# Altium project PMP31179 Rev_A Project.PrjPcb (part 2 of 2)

## Sheet PMP31179 Rev_A LLC Schematic.SchDoc: LLC
size 431 x 317 mm; Date: Not shown in title block; ApprovedBy: Not shown in title block; CheckedBy: Not shown in title block; Author: Not shown in title block; CompanyName: Not shown in title block; DrawnBy: R. Scibilia; Engineer: R. Scibilia; Organization: Not shown in title block; Address1: Not shown in title block; Address2: Not shown in title block; Address3: Not shown in title block; Address4: Not shown in title block; DocumentNumber: 1; Revision: Use project parameter SCH_Rev; SheetNumber: 2; SheetTotal: 3; PageSetup: Record=PageOptions¦CenterHorizontal=True¦CenterVertical=True¦PrintScale=1.00¦XCorrection=1.00¦YCorrection=1.00¦PrintKind=0¦BorderSize=5000000¦LeftOffset=0¦BottomOffset=0¦Orientation=2¦PaperLength=1000¦PaperWidth=1000¦Scale=100¦PaperSource=15¦PrintQuality=600¦MediaType=1¦DitherType=10¦PaperKind=Letter¦PrintScaleMode=1
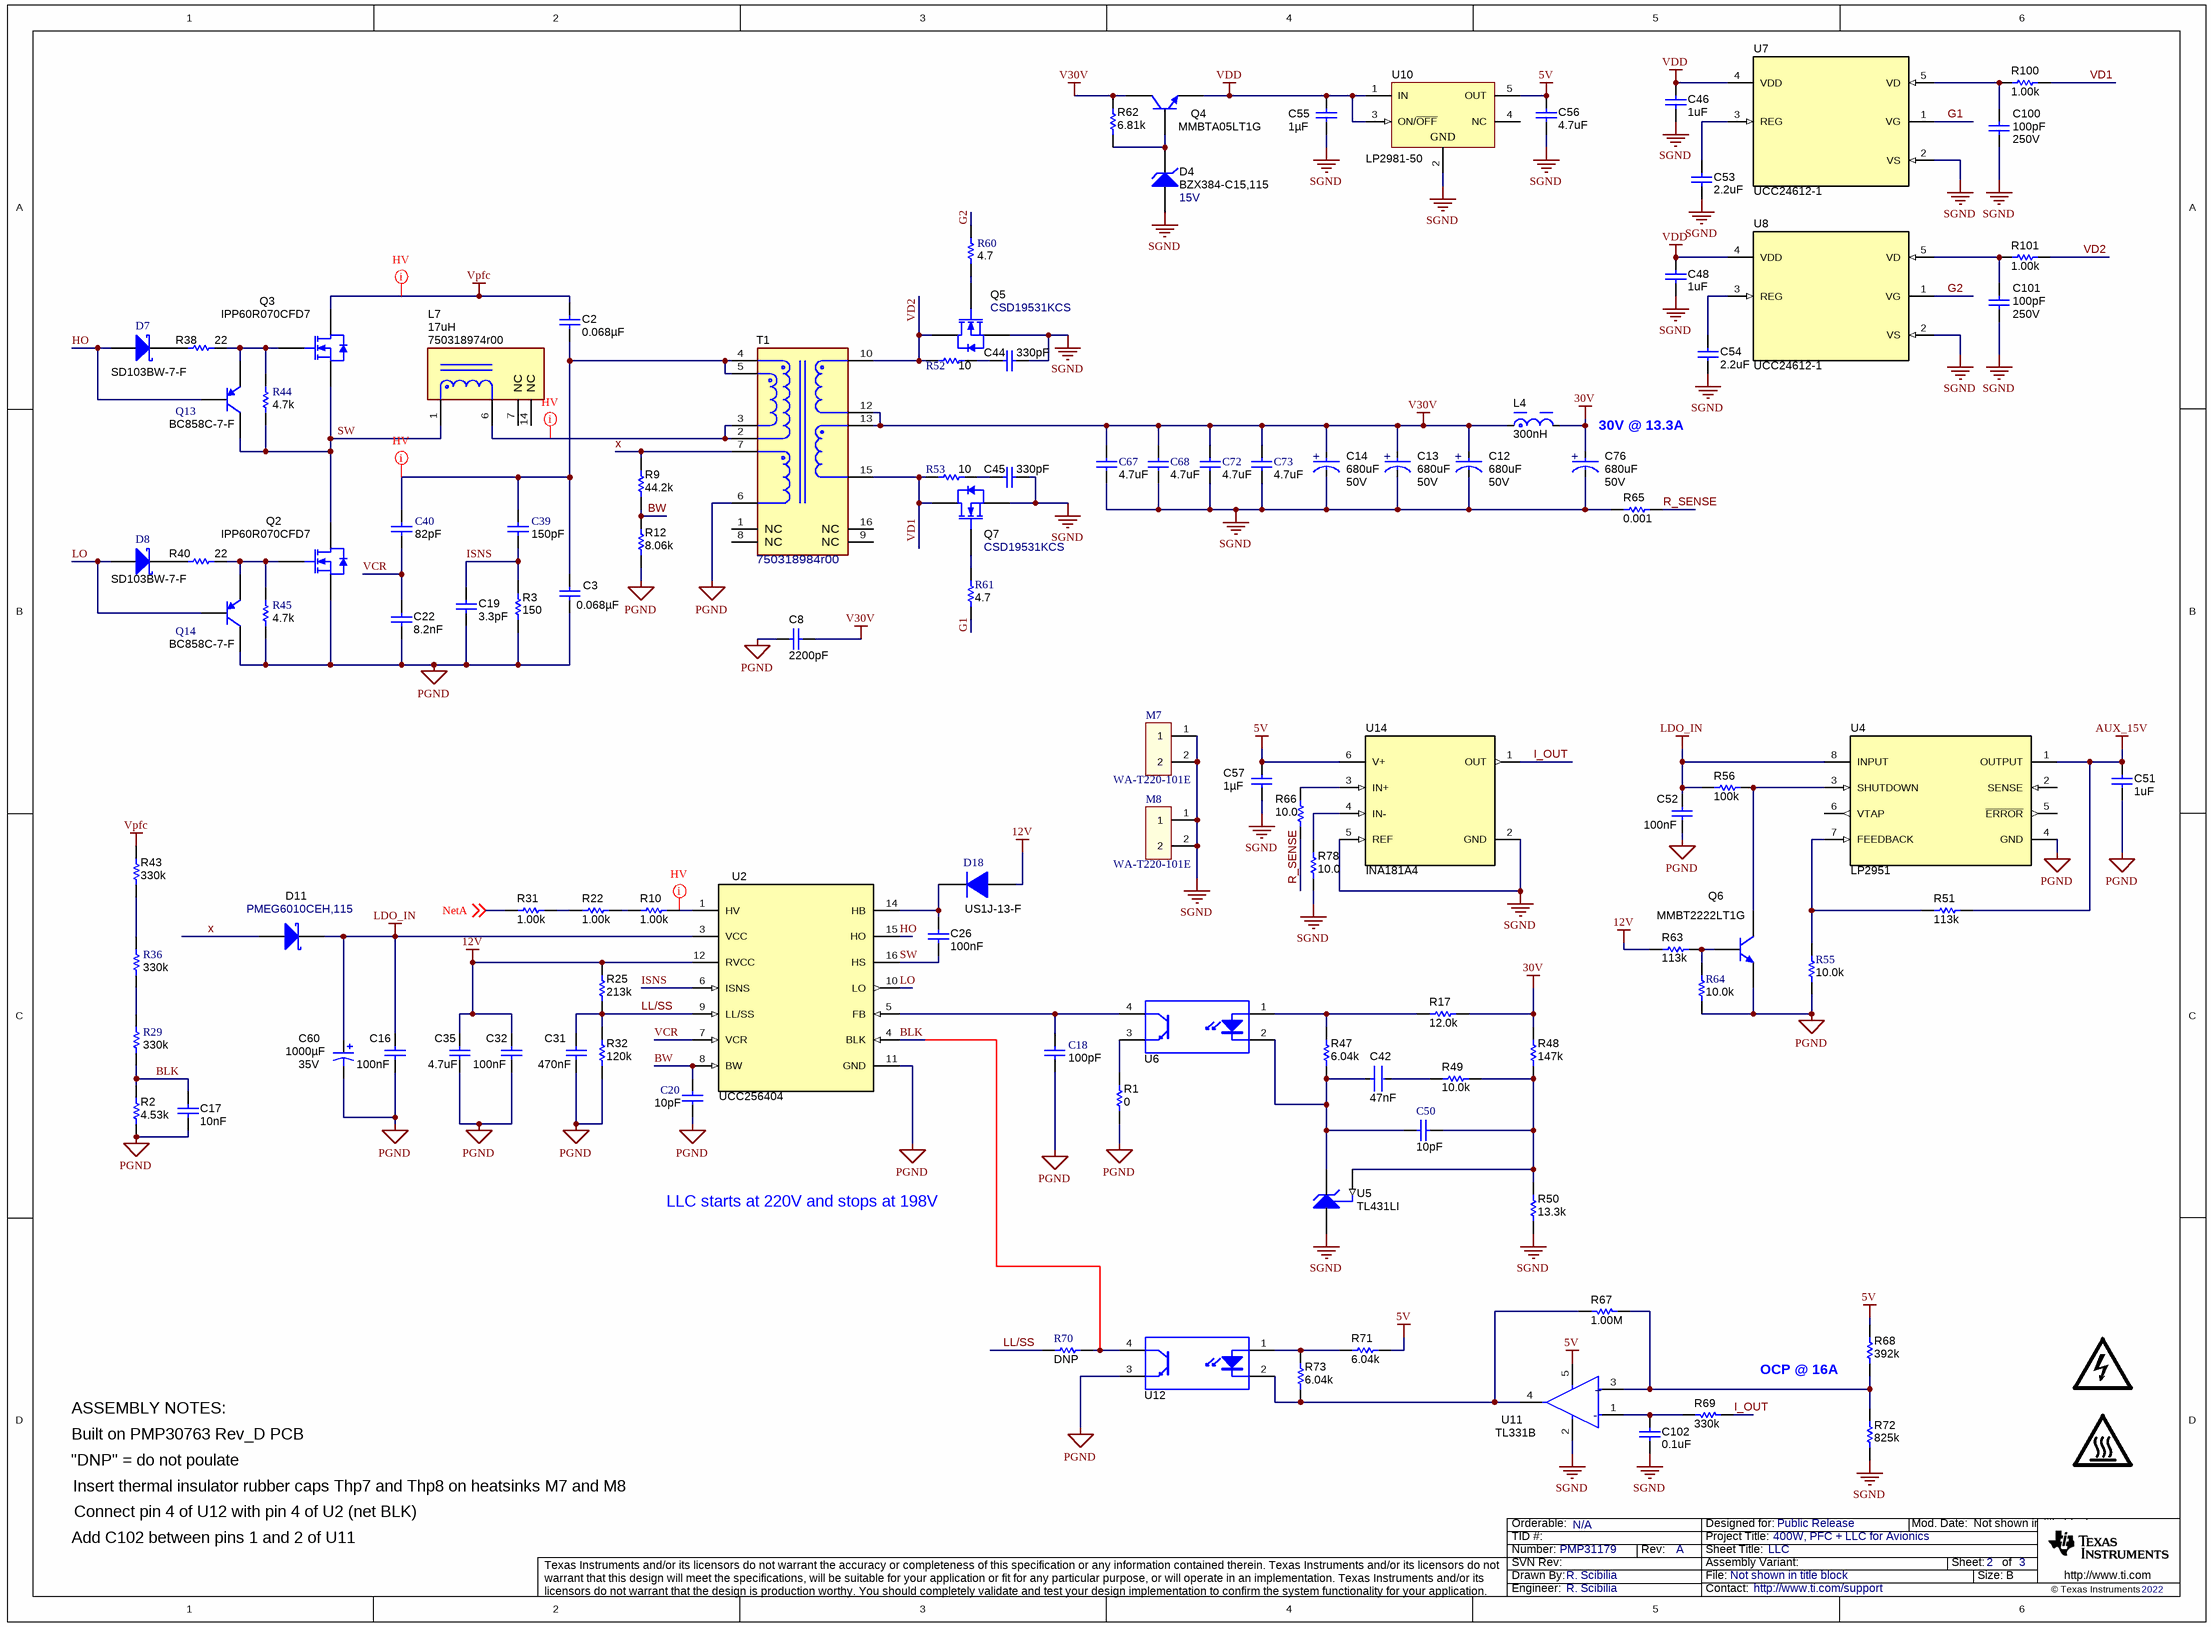
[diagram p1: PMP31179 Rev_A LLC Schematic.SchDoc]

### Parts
(Parts that share a designator on the sheet are numbered #1, #2 ... from top to bottom, then left to right.)
C2  ValueDisplayed: 0.068µF  [B32652_1800x700x1250]  (hidden comment: B32642B6683J)
C3  ValueDisplayed: 0.068µF  [B32652_1800x700x1250]  (hidden comment: B32642B6683J)
C8  ValueDisplayed: 2200pF  [AY2_950x500_Straight]  (hidden comment: Capacitor)
C12  value 680uF  VDC_V: 50V  [FP-860080678019_RADIAL-MFG]  (hidden comment: 860080678021)
C13  value 680uF  VDC_V: 50V  [FP-860080678019_RADIAL-MFG]  (hidden comment: 860080678021)
C14  value 680uF  VDC_V: 50V  [FP-860080678019_RADIAL-MFG]  (hidden comment: 860080678021)
C16  Cap_F: 100nF  [0603]  (hidden comment: 885012206095)
C17  Cap_F: 10nF  [0603]  (hidden comment: 885012206040)
C18  ValueDisplayed: 100pF  [0603]  (hidden comment: 885012006023)
C19  ValueDisplayed: 3.3pF  [0805_HV1]  (hidden comment: Capacitor)
C20  ValueDisplayed: 10pF  [0603]  (hidden comment: Capacitor)
C22  Cap_F: 8.2nF  [0603]  (hidden comment: GRM188R71H822KA01D)
C26  Cap_F: 100nF  [0805_HV]  (hidden comment: 885012207128)
C31  Cap_F: 470nF  [0805_HV]  (hidden comment: 885012207102)
C32  Cap_F: 100nF  [0603]  (hidden comment: 885012206095)
C35  ValueDisplayed: 4.7uF  [0603]  (hidden comment: GRM188R61E475KE11D)
C39  ValueDisplayed: 150pF  [1206]  (hidden comment: Capacitor)
C40  ValueDisplayed: 82pF  [1206]  (hidden comment: GRM31A7U3A820JW31D)
C42  Cap_F: 47nF  [FP-885012206069_0603-MFG]  (hidden comment: 885012206069)
C44  ValueDisplayed: 330pF  [1206]  (hidden comment: 885012008070)
C45  ValueDisplayed: 330pF  [1206]  (hidden comment: 885012008070)
C46  ValueDisplayed: 1uF  [0805_HV1]  (hidden comment: Capacitor)
C48  ValueDisplayed: 1uF  [0805_HV1]  (hidden comment: Capacitor)
C50  ValueDisplayed: 10pF  [0603]  (hidden comment: Capacitor)
C51  ValueDisplayed: 1uF  [1206]  (hidden comment: Capacitor)
C52  Cap_F: 100nF  [0603]  (hidden comment: 885012206095)
C53  ValueDisplayed: 2.2uF  [0603]  (hidden comment: GRM188R6YA225KA12D)
C54  ValueDisplayed: 2.2uF  [0603]  (hidden comment: GRM188R6YA225KA12D)
C55  Cap_F: 1µF  [0603]  (hidden comment: 885012206076)
C56  ValueDisplayed: 4.7uF  [0603]  (hidden comment: GRM188R61E475KE11D)
C57  Cap_F: 1µF  [0603]  (hidden comment: 885012206076)
C60  value 1000µF  VDC_V: 35V  [Panasonic_1000x1250]  (hidden comment: 860160575031)
C67  ValueDisplayed: 4.7uF  [1210]  (hidden comment: Capacitor)
C68  ValueDisplayed: 4.7uF  [1210]  (hidden comment: Capacitor)
C72  ValueDisplayed: 4.7uF  [1210]  (hidden comment: Capacitor)
C73  ValueDisplayed: 4.7uF  [1210]  (hidden comment: Capacitor)
C76  value 680uF  VDC_V: 50V  [FP-860080678019_RADIAL-MFG]  (hidden comment: 860080678021)
C100  VDC_V: 250V  ValueDisplayed: 100pF  [0805_HV]  (hidden comment: 885342006003)
C101  VDC_V: 250V  ValueDisplayed: 100pF  [0805_HV]  (hidden comment: 885342006003)
C102  ValueDisplayed: 0.1uF  [0805_HV1]  (hidden comment: Capacitor)
D4  BZX384-C15,115  value 15V  [SOD-323]
D7  value SD103BW-7-F  [SOD-123]  (hidden comment: DIODE_SCHOTTKY)
D8  value SD103BW-7-F  [SOD-123]  (hidden comment: DIODE_SCHOTTKY)
D11  PMEG6010CEH,115  [SOD-123F]
D18  value US1J-13-F  [SMA]  (hidden comment: DIODE)
L4  value 300nH  [FP-7443081030_SMT_IND_9MM4_6MM2-MFG]  (hidden comment: 7443081030)
L7  value 17uH  [FP-750318974r00_PTH_23MM88_23MM36-MFG]  (hidden comment: 750318974r00)
LOGO?#3  DANGER HIGH VOLTAGE  [IEC_HighVoltage_Small]  (value not drawn)  (graphical)
LOGO?#4  CAUTION HOT SURFACE  [IEC_HotSurface_Small]  (value not drawn)  (graphical)
M7  WA-T220-101E  [HEATSINK_WA-T220-101E]
M8  WA-T220-101E  [HEATSINK_WA-T220-101E]
Q2  value IPP60R070CFD7  [TO-220AB]  (hidden comment: IPP60R190P6)
Q3  value IPP60R070CFD7  [TO-220AB]  (hidden comment: IPP60R190P6)
Q4  MMBTA05LT1G  [SOT-23]
Q5  CSD19531KCS  [KCS0003B]
Q6  MMBT2222LT1G  [SOT-23]
Q7  CSD19531KCS  [KCS0003B]
Q13  BC858C-7-F  [SOT-23]
Q14  BC858C-7-F  [SOT-23]
R1  ValueDisplayed: 0  [0603]  (hidden comment: RMCF0603ZT0R00)
R2  ValueDisplayed: 4.53k  [0603]  (hidden comment: ERJ-3EKF4531V)
R3  ValueDisplayed: 150  [0805_HV]  (hidden comment: CRCW0805150RFKEA)
R9  ValueDisplayed: 44.2k  [0603]  (hidden comment: CRCW060344K2FKEA)
R10  ValueDisplayed: 1.00k  [1206]  (hidden comment: Resistor)
R12  ValueDisplayed: 8.06k  [0603]  (hidden comment: RC0603FR-078K06L)
R17  ValueDisplayed: 12.0k  [0603]  (hidden comment: RC0603FR-0712KL)
R22  ValueDisplayed: 1.00k  [1206]  (hidden comment: Resistor)
R25  ValueDisplayed: 213k  [0603]  (hidden comment: RT0603DRE07213KL)
R29  ValueDisplayed: 330k  [1206]  (hidden comment: Resistor)
R31  ValueDisplayed: 1.00k  [1206]  (hidden comment: Resistor)
R32  ValueDisplayed: 120k  [0603]  (hidden comment: RC0603FR-07120KL)
R36  ValueDisplayed: 330k  [1206]  (hidden comment: Resistor)
R38  ValueDisplayed: 22  [0603]  (hidden comment: Resistor)
R40  ValueDisplayed: 22  [0603]  (hidden comment: Resistor)
R43  ValueDisplayed: 330k  [1206]  (hidden comment: CRCW1206330KJNEA)
R44  ValueDisplayed: 4.7k  [0603]  (hidden comment: Resistor)
R45  ValueDisplayed: 4.7k  [0603]  (hidden comment: Resistor)
R47  ValueDisplayed: 6.04k  [0603]  (hidden comment: Resistor)
R48  ValueDisplayed: 147k  [0603]  (hidden comment: Resistor)
R49  ValueDisplayed: 10.0k  [0603]  (hidden comment: Resistor)
R50  ValueDisplayed: 13.3k  [0603]  (hidden comment: RC0603FR-0713K3L)
R51  ValueDisplayed: 113k  [0603]  (hidden comment: CRCW0603113KFKEA)
R52  ValueDisplayed: 10  [0805_HV1]  (hidden comment: Resistor)
R53  ValueDisplayed: 10  [0805_HV1]  (hidden comment: Resistor)
R55  ValueDisplayed: 10.0k  [0603]  (hidden comment: Resistor)
R56  ValueDisplayed: 100k  [0603]  (hidden comment: RT0603BRD07100KL)
R60  ValueDisplayed: 4.7  [0805_HV1]  (hidden comment: Resistor)
R61  ValueDisplayed: 4.7  [0805_HV1]  (hidden comment: Resistor)
R62  ValueDisplayed: 6.81k  [0603]  (hidden comment: RC0603FR-076K81L)
R63  ValueDisplayed: 113k  [0603]  (hidden comment: CRCW0603113KFKEA)
R64  ValueDisplayed: 10.0k  [0603]  (hidden comment: Resistor)
R65  ValueDisplayed: 0.001  [WSL2512_-0005]  (hidden comment: WSL2512R0010FEA18)
R66  ValueDisplayed: 10.0  [0603]  (hidden comment: CRCW060310R0FKEAHP)
R67  ValueDisplayed: 1.00M  [0805_HV]  (hidden comment: CRCW08051M00FKEA)
R68  ValueDisplayed: 392k  [0603]  (hidden comment: RC0603FR-07392KL)
R69  ValueDisplayed: 330k  [0603]  (hidden comment: ERJ-3EKF3303V)
R70  DNP  [0603]
R71  ValueDisplayed: 6.04k  [0603]  (hidden comment: Resistor)
R72  ValueDisplayed: 825k  [0603]  (hidden comment: RC0603FR-07825KL)
R73  ValueDisplayed: 6.04k  [0603]  (hidden comment: Resistor)
R78  ValueDisplayed: 10.0  [0603]  (hidden comment: CRCW060310R0FKEAHP)
R100  ValueDisplayed: 1.00k  [0603]  (hidden comment: ERJ-3EKF1001V)
R101  ValueDisplayed: 1.00k  [0603]  (hidden comment: ERJ-3EKF1001V)
T1  750318984r00  [FP-750318984r00_PTH_41MM9_49MM0-MFG]
U2  value UCC256404  [DDB0014A]  (hidden comment: UCC256404DDBR)
U4  value LP2951  [D0008A_N]  (hidden comment: LP2951DR)
U5  value TL431LI  [DBZ0003A_N]  (hidden comment: TL431LIAIDBZR)
U6  Opto-Isolator  [DIP-4]  (value not drawn)
U7  value UCC24612-1  [DBV0005A_N]  (hidden comment: UCC24612-1DBVR)
U8  value UCC24612-1  [DBV0005A_N]  (hidden comment: UCC24612-1DBVR)
U10  LP2981-50  [DBV0005A_N]
U11  value TL331B  [DBV0005A-MFG]  (hidden comment: TL331BIDBVR)
U12  Opto-Isolator  [DIP-4]  (value not drawn)
U14  value INA181A4  [DBV0006A_N]  (hidden comment: INA181A4IDBVR)

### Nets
5V: C56.1 C57.1 R68.2 R71.2 U10.5(OUT) U11.5(VCC) U14.6(V+)
12V: C32.1 C35.2 D18.2(A) R25.2 R63.1 U2.12(RVCC)
30V: C76.2(ANODE) L4.2 R17.2 R48.2
AUX_15V: C51.1 R51.2 U4.1(OUTPUT)
LDO_IN: C16.1 C52.1 C60.1(+) D11.1(K) R56.2 U2.3(VCC) U4.8(INPUT)
PGND: C3.2 C8.2 C16.2 C17.2 C18.2 C19.2 C20.2 C22.2 C31.2 C32.2 C35.1 C51.2 C52.2 C60.2(-) Q2.3(S) Q6.2(E) Q14.3(C) R1.1 R2.1 R3.1 R12.1 R32.1 R45.1 R55.1 R64.1 T1.6 U2.11(GND) U4.4(GND) U12.3(E)
SGND: C12.1(CATHODE) C13.1(CATHODE) C14.1(CATHODE) C44.1 C45.1 C46.2 C48.2 C53.2 C54.2 C55.2 C56.2 C57.2 C67.2 C68.2 C72.2 C73.2 C76.1(CATHODE) C100.2 C101.2 C102.2 D4.2(A) M7.1 M7.2 M8.1 M8.2 Q5.3(S) Q7.3(S) R50.1 R65.1 R72.1 R78.1 U5.3(ANODE) U7.2(VS) U8.2(VS) U10.2(GND) U11.2(GND) U14.2(GND) U14.5(REF)
V30V: C8.1 C12.2(ANODE) C13.2(ANODE) C14.2(ANODE) C67.1 C68.1 C72.1 C73.1 L4.1 Q4.3(C) R62.2 T1.12 T1.13
VDD: C46.1 C48.1 C55.1 Q4.2(E) U7.4(VDD) U8.4(VDD) U10.1(IN) U10.3(ON/~{OFF})
Vpfc: C2.1 Q3.2(D) R43.2
BLK: C17.1 R2.2 R29.1 R70.1 U2.4(BLK) U12.4(C)
BW: C20.1 R9.1 R12.2 U2.8(BW)
G1: R61.1 U7.1(VG)
G2: R60.2 U8.1(VG)
HO: D7.2(A) Q13.1(B) U2.15(HO)
I_OUT: R69.1 U14.1(OUT)
ISNS: C19.1 C39.2 R3.2 U2.6(ISNS)
LL/SS: C31.1 R25.1 R32.2 R70.2 U2.9(LL/SS)
LO: D8.2(A) Q14.1(B) U2.10(LO)
NetA: R31.1 ; off-sheet NetA
R_SENSE: R65.2 R66.1
SW: C26.2 L7.1 Q2.2(D) Q3.3(S) Q13.3(C) R44.1 U2.16(HS)
VCR: C22.1 C40.2 U2.7(VCR)
VD1: Q7.2(D) R53.1 R100.2 T1.15
VD2: Q5.2(D) R52.1 R101.2 T1.10
x: D11.2(A) R9.2 T1.7
NetC2_2: C2.2 C3.1 C39.1 C40.1 T1.4 T1.5
NetC18_1: C18.1 U2.5(FB) U6.4(C)
NetC26_1: C26.1 D18.1(K) U2.14(HB)
NetC42_1: C42.1 C50.1 R47.1 U5.1(CATHODE) U6.2(K)
NetC42_2: C42.2 R49.1
NetC44_2: C44.2 R52.2
NetC45_2: C45.2 R53.2
NetC50_2: C50.2 R48.1 R49.2 R50.2 U5.2(REF)
NetC53_1: C53.1 U7.3(REG)
NetC54_1: C54.1 U8.3(REG)
NetC100_1: C100.1 R100.1 U7.5(VD)
NetC101_1: C101.1 R101.1 U8.5(VD)
NetC102_1: C102.1 R69.2 U11.1(IN-)
NetD4_1: D4.1(K) Q4.1(B) R62.1
NetD7_1: D7.1(K) R38.1
NetD8_1: D8.1(K) R40.1
NetL7_6: L7.6 T1.2 T1.3
NetQ2_1: Q2.1(G) Q14.2(E) R40.2 R45.2
NetQ3_1: Q3.1(G) Q13.2(E) R38.2 R44.2
NetQ5_1: Q5.1(G) R60.1
NetQ6_1: Q6.1(B) R63.2 R64.2
NetQ6_3: Q6.3(C) R56.1 U4.3(SHUTDOWN)
NetQ7_1: Q7.1(G) R61.2
NetR1_2: R1.2 U6.3(E)
NetR10_1: R10.1 R22.2
NetR10_2: R10.2 U2.1(HV)
NetR17_1: R17.1 R47.2 U6.1(A)
NetR22_1: R22.1 R31.2
NetR29_2: R29.2 R36.1
NetR36_2: R36.2 R43.1
NetR51_1: R51.1 R55.2 U4.7(FEEDBACK)
NetR66_2: R66.2 U14.3(IN+)
NetR67_1: R67.1 R68.1 R72.2 U11.3(IN+)
NetR67_2: R67.2 R73.1 U11.4(OUT) U12.2(K)
NetR71_1: R71.1 R73.2 U12.1(A)
NetR78_2: R78.2 U14.4(IN-)

Not connected (* = marked no-connect by the designer): L7 7(NC) 14(NC); T1 1(NC) 8(NC) 9(NC) 16(NC); U4 2(SENSE) 5(~{ERROR}) 6(VTAP); U10 4(NC)

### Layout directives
net class HV: NetC2_2, NetL7_6, NetR10_2, Vpfc

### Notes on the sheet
- 30V @ 13.3A
- LLC starts at 220V and stops at 198V
- OCP @ 16A
- ASSEMBLY NOTES:
- Built on PMP30763 Rev_D PCB
- "DNP" = do not poulate
- Connect pin 4 of U12 with pin 4 of U2 (net BLK)
- Insert thermal insulator rubber caps Thp7 and Thp8 on heatsinks M7 and M8
- Add C102 between pins 1 and 2 of U11

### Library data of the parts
C2 C3 = B32652A7153J000: CAP FILM 0.068UF 10% 630VDC RAD; Manufacturer: EPCOS (TDK); Polarized: N; CompType: Capacitor; U/M: EA; Cap_F: 0.000000068; Tolerance_%: 5; VDC_V: 630; Value2: 630V; TaMin_C: -55; TaMax_C: 100; Cap_Case: 18x8x12.5; SizeAreaWB_mm2: 180; SizeArea_mm2: 126; SizeX_mm: 18; SizeY_mm: 8; SizeZ_mm: 12.5; AEC Category: Q200; AEC Qualified: Y; AEC Grade: 3; Green_Lifecycle: Not Set; Green_REACh: Incomplete; VAC: 250
C8 = CMP-0009587-2: CAP, CERM, 2200 pF, 300 V, +/- 20%, Y5U, AEC-Q200 Grade 1, D9.5xT5mm; PartNumber: AY2222M35Y5US63L7; Manufacturer: Vishay-Bccomponents; Polarized: N; Value: 2200pF; U/M: EA; Cap_F: 2.2nF; Value1: Unknown; VDC_V: 300V; TaMin_C: -55°C; TaMax_C: 125°C; Cap_Case: 9.5x5mm; SizeArea_mm2: 47.5; SizeAreaWB_mm2: 80.5; SizeX_mm: 9.5; SizeY_mm: 5; SizeZ_mm: 14.5; AEC Category: Q200; AEC Qualified: Y; AEC Grade: 1
C12-C14 C76 = CMP-0087158-1: CAP ALUM 680UF 20% 50V THRU HOLE; Manufacturer: Wurth Electronics; Symbol Name: SYM-860080678019; IRMS_A: 2.5A; SizeZ_mm: 25mm; Cap_F: 680µF; AEC Qualified: No
C16 C32 C52 = CMP-0006837-3: CAP, CERM, 0.1 uF, 50 V, +/- 10%, X7R, 0603; Manufacturer: Wurth Elektronik; TaMin_C: -55°C; Polarized: N; SizeAreaWB_mm2: 4.68; Value1: Unknown; U/M: EA; Value: 0.1uF; TaMax_C: 125°C; SizeZ_mm: 1; SizeX_mm: 1.6; SizeY_mm: 0.8; Value2: 50V; SizeArea_mm2: 1.28; AEC Category: Q200
C17 = CMP-0006828-3: CAP, CERM, 0.01 uF, 16 V, +/- 10%, X7R, 0603; Manufacturer: Wurth Elektronik; TaMin_C: -55°C; Polarized: N; SizeAreaWB_mm2: 4.68; Value1: Unknown; U/M: EA; Value: 0.01uF; TaMax_C: 125°C; SizeZ_mm: 1; SizeX_mm: 1.6; SizeY_mm: 0.8; Value2: 16V; SizeArea_mm2: 1.28; AEC Category: Q200
C18 = C0603C101J5GAC: CAP CER 100PF 16V C0G/NP0 0603; Manufacturer: Wurth Electronics Inc.; Polarized: N; CompType: Capacitor; U/M: EA; Cap_F: 0.0000000001; Tolerance_%: 5; Value1: Unknown; VDC_V: 16; TaMin_C: -55; TaMax_C: 125
C19 = CMP-0007612-2: CAP, CERM, 3.3 pF, 50 V, +/- 8%, C0G/NP0, 0805; PartNumber: 885012007048; Manufacturer: Wuerth; Polarized: N; Value: 3.3pF; U/M: EA; ESR_ohm: 3.467; Value1: 3.467 ohm; VDC_V: 50V; TaMin_C: -55°C; TaMax_C: 125°C; Cap_Case: 0805; SizeArea_mm2: 2.5; SizeAreaWB_mm2: 6.75; SizeX_mm: 2; SizeY_mm: 1.25; SizeZ_mm: 1.45; AEC Category: Q200
C20 C50 = CMP-0006761-4: CAP, CERM, 10 pF, 50 V, +/- 5%, C0G/NP0, 0603; PartNumber: 885012006051; Manufacturer: Wuerth; Polarized: N; Value: 10pF; U/M: EA; ESR_ohm: 0.403; Value1: 0.403 ohm; VDC_V: 50V; TaMin_C: -55°C; TaMax_C: 125°C; AEC Category: Q200; SizeArea_mm2: 1.28; SizeAreaWB_mm2: 4.68; SizeX_mm: 1.6; SizeY_mm: 0.8; SizeZ_mm: 1
C22 = CMP-0007465-4: CAP, CERM, 8200 pF, 50 V, +/- 10%, X7R, 0603; Manufacturer: MuRata; TaMin_C: -55°C; Polarized: N; SizeAreaWB_mm2: 4.68; Value1: Unknown; U/M: EA; Value: 8200pF; TaMax_C: 125°C; SizeZ_mm: 1; SizeX_mm: 1.6; SizeY_mm: 0.8; Value2: 50V; SizeArea_mm2: 1.28; AEC Category: Q200
C26 = CMP-0750058-1: CAP, CERM, 0.1 µF, 100 V,+/- 10%, X7R, 0805; Manufacturer: Wurth Elektronik; TaMin_C: -55°C; AEC Category: Q200; U/M: EA; SizeY_mm: 1.25; Polarized: N; Value: 0.1uF; SizeX_mm: 2; TaMax_C: 125°C; ValueDisplayed: 0.1µF; SizeArea_mm2: 2.5; Cap_Case: 0805; VDC_V: 100V; SizeZ_mm: 1.45; SizeAreaWB_mm2: 6.75
C31 = CMP-0007695-2: CAP, CERM, 0.47 uF, 50 V, +/- 10%, X7R, 0805; Manufacturer: Wurth Elektronik; TaMin_C: -55°C; Polarized: N; SizeAreaWB_mm2: 6.75; Value1: Unknown; U/M: EA; Value: 0.47uF; TaMax_C: 125°C; SizeZ_mm: 1.45; SizeX_mm: 2; SizeY_mm: 1.25; Cap_Case: 0805; Value2: 50V; SizeArea_mm2: 2.5; AEC Category: Q200
C35 C56 = CMP-0007347-5: CAP, CERM, 4.7 uF, 25 V, +/- 10%, X5R, 0603; Manufacturer: MuRata; TaMin_C: -55°C; Polarized: N; SizeAreaWB_mm2: 4.68; Value1: Unknown; U/M: EA; Value: 4.7uF; TaMax_C: 85°C; SizeZ_mm: 1; SizeX_mm: 1.6; SizeY_mm: 0.8; Value2: 25V; SizeArea_mm2: 1.28; CompType: Capacitor; Cap_F: 4.7µF; AEC Category: Q200
C39 = CMP-0008898-2: CAP, CERM, 150 pF, 1000 V, +/- 5%, U2J, 1206; PartNumber: GRM31A7U3A151JW31D; Manufacturer: MuRata; Polarized: N; Value: 150pF; U/M: EA; Value1: Unknown; VDC_V: 1kV; Value2: 1000V; TaMin_C: -55°C; TaMax_C: 125°C; AEC Category: Q200; SizeArea_mm2: 5.12; SizeAreaWB_mm2: 10.92; SizeX_mm: 3.2; SizeY_mm: 1.6; SizeZ_mm: 1.35
C40 = GRM31A7U3A151JW31D: CAP CER 82PF 1KV U2J 1206; Manufacturer: MuRata; Polarized: N; CompType: Capacitor; U/M: EA; Cap_F: 0.000000000082; Tolerance_%: 5; Value1: Unknown; VDC_V: 1000; Value2: 1000V; TaMin_C: -55; TaMax_C: 125
C42 = CMP-0086483-1: 0.047µF ±10% 25V Ceramic Capacitor X7R 0603 (1608 Metric); Manufacturer: Wurth Electronics; SizeZ_mm: 0.95mm; TempCo: 15%; Symbol Name: SYM-885012206069; AEC Qualified: No
C44 C45 = CMP-0008475-2: CAP, CERM, 330 pF, 100 V, +/- 5%, C0G/NP0, 1206; Manufacturer: Wuerth; TaMin_C: -55°C; ESR_ohm: 3.92d; Polarized: N; SizeAreaWB_mm2: 10.92; Value1: 0.392 ohm; U/M: EA; Value: 330pF; TaMax_C: 125°C; SizeZ_mm: 1.35; SizeX_mm: 3.2; SizeY_mm: 1.6; Value2: 100V; SizeArea_mm2: 5.12; CompType: Capacitor; AEC Category: Q200
C46 C48 = CMP-0007728-2: CAP, CERM, 1 uF, 25 V, +/- 10%, X7R, 0805; PartNumber: 885012207078; Manufacturer: Wuerth; Polarized: N; Value: 1uF; U/M: EA; Cap_F: 1µF; Value1: Unknown; VDC_V: 25V; TaMin_C: -55°C; TaMax_C: 125°C; Cap_Case: 0805; SizeArea_mm2: 2.5; SizeAreaWB_mm2: 6.75; SizeX_mm: 2; SizeY_mm: 1.25; SizeZ_mm: 1.45; AEC Category: Q200
C51 = CMP-0008863-2: CAP, CERM, 1 uF, 25 V, +/- 10%, X5R, 1206; PartNumber: 885012208064; Manufacturer: Wuerth; Polarized: N; Value: 1uF; U/M: EA; Cap_F: 1µF; ESR_ohm: 10m; Value1: 0.01 ohm; VDC_V: 25V; TaMin_C: -55°C; TaMax_C: 85°C; AEC Category: Q200; SizeArea_mm2: 5.12; SizeAreaWB_mm2: 10.92; SizeX_mm: 3.2; SizeY_mm: 1.6; SizeZ_mm: 1.35
C53 C54 = CMP-0007356-5: CAP, CERM, 2.2 uF, 35 V, +/- 10%, X5R, 0603; Manufacturer: MuRata; TaMin_C: -55°C; Polarized: N; SizeAreaWB_mm2: 4.68; Value1: Unknown; U/M: EA; Value: 2.2uF; TaMax_C: 85°C; SizeZ_mm: 1; SizeX_mm: 1.6; SizeY_mm: 0.8; Value2: 35V; SizeArea_mm2: 1.28; CompType: Capacitor; Cap_F: 2.2µF; AEC Category: Q200
C55 C57 = CMP-0006833-4: CAP, CERM, 1 uF, 25 V, +/- 10%, X7R, 0603; Manufacturer: Wurth Elektronik; TaMin_C: -55°C; Polarized: N; SizeAreaWB_mm2: 4.68; Value1: Unknown; U/M: EA; Value: 1uF; TaMax_C: 125°C; SizeZ_mm: 1; SizeX_mm: 1.6; SizeY_mm: 0.8; Value2: 25V; SizeArea_mm2: 1.28; AEC Category: Q200
C60 = CMP-0064896-2: 1000µF 35V Aluminum Electrolytic Capacitors Radial, Can 6000 Hrs @ 105°C; Manufacturer: Wuerth; TaMin_C: -55°C; ESR_ohm: 0.06; Polarized: Y; SizeAreaWB_mm2: 144; U/M: EA; Tolerance_%: 20%; SizeZ_mm: 30; SizeX_mm: 10; Cap_Case: 10x30; SizeArea_mm2: 100; IRMS_A: 2.136A; AEC Grade: 2; AEC Category: Q200
C67 C68 C72 C73 = CMP-0009135-2: CAP, CERM, 4.7 uF, 100 V, +/- 10%, X7S, 1210; PartNumber: C3225X7S2A475K200AE; Manufacturer: TDK; Polarized: N; Value: 4.7uF; U/M: EA; Cap_F: 4.7µF; Value1: Unknown; VDC_V: 100V; TaMin_C: -55°C; TaMax_C: 125°C; AEC Category: Q200; SizeArea_mm2: 8; SizeAreaWB_mm2: 14.7; SizeX_mm: 3.2; SizeY_mm: 2.5; SizeZ_mm: 1.35
C100 C101 = CMP-0008236-2: CAP, CERM, 100 pF, 250 V, +/- 5%, C0G/NP0, 0603; Manufacturer: Wuerth; TaMin_C: -55°C; Polarized: N; SizeAreaWB_mm2: 6.75; Value1: Unknown; U/M: EA; Value: 100pF; TaMax_C: 125°C; SizeZ_mm: 1.45; SizeX_mm: 2; SizeY_mm: 1.25; Cap_Case: 0603; SizeArea_mm2: 2.5; AEC Category: Q200
C102 = CMP-0007722-2: CAP, CERM, 0.1 uF, 100 V, +/- 10%, X7R, 0805; PartNumber: C0805C104K1RACTU; Manufacturer: Kemet; Polarized: N; Value: 0.1uF; U/M: EA; Cap_F: 100nF; ESR_ohm: 64m; Value1: 0.064 ohm; VDC_V: 100V; IRMS_A: 1.64A; TaMin_C: -55°C; TaMax_C: 125°C; Cap_Case: 0805; SizeArea_mm2: 2.5; SizeAreaWB_mm2: 6.75; SizeX_mm: 2; SizeY_mm: 1.25; SizeZ_mm: 1.45; AEC Category: Q200
D4 = CMP-0005844-4: Diode, Zener, 15 V, 300 mW, SOD-323; Manufacturer: NXP Semiconductor; Power_W: 300mW; SizeAreaWB_mm2: 8.695; Value1: 0.3W; RJA_CperW: 415; SizeZ_mm: 1; SizeX_mm: 2.7; SizeY_mm: 1.35; SizeArea_mm2: 3.645; AEC Category: Q101
D7 D8 = CMP-0028545-2: Diode, Schottky, 30 V, 0.35 A, SOD-123; Manufacturer: Diodes Inc.; Vf_V: 550mV; Value1: 0.35A; Value2: 0.55V; Io_A: 350mA; Vr_V: 30V; AEC Category: Q101; Green_Lifecycle: Not Set; Green_REACh: Incomplete; SizeArea_mm2: 6.545; SizeAreaWB_mm2: 13.095; SizeX_mm: 3.85; SizeY_mm: 1.7; SizeZ_mm: 1.35
D11 = CMP-0028377-2: Diode, Schottky, 60 V, 1 A, SOD-123F; Manufacturer: Nexperia; Value1: 1A; Value2: 0.57V; TJmax_C: 150°C; Green_REACh: Incomplete; Vr_V: 60V; SizeY_mm: 1.6; Vf_V: 570mV; SizeArea_mm2: 5.6; AEC Category: Q101; SizeZ_mm: 1.1; SizeX_mm: 3.5; Green_Lifecycle: Not Set; SizeAreaWB_mm2: 11.7
D18 = CMP-0077027-2: Diode, Ultrafast, 600 V, 1 A, SMA; Manufacturer: Diodes Inc.; Vf_V: 1.7V; Io_A: 1A; Vr_V: 600V; TJmax_C: 150°C; AEC Category: Q101; Green_Lifecycle: Active; Green_REACh: Passed; SizeArea_mm2: 16.3228; SizeAreaWB_mm2: 37.3428; SizeX_mm: 5.59; SizeY_mm: 2.92; SizeZ_mm: 2.87
L4 = CMP-0093738-1: WE-HCM SMT High Current Flat Wire Inductor 34.6A 300nH @ 10% 100kHz 0.3045mohm; Manufacturer: Wurth Electronics; AEC Qualified: No; Self Resonant Frequency: 33MHz; SizeZ_mm: 8.1mm; TaMin_C: -40°C; Isat: 22.2A; Shrouded: true; TaMax_C: +85°C; DCR_ohm: 304.5µ
L7 = CMP-0088744-1: INDUCTOR, 17uH, 20A; Manufacturer: Wurth Electronics; AEC Qualified: No; DCR_ohm: 22.8m; Test Frequency: 10kHz; Ind_H: 17µH; Tolerance_%: 10%; SizeZ_mm: 24.14mm
LOGO?#3 = IEC_HighVoltage: IEC 61010-1 High Voltage Warning; SymbolCreator: a0412235
LOGO?#4 = IEC_HotSurface: IEC 61010-1 Hot Surface Warning; SymbolCreator: a0412235
M7 M8 = WA-T220-101E: HEATSINK, ALUMINIUM WITH CLIP, VERTICAL MOUNT, SOLDERABLE PIN, TO-220; Manufacturer: OHMITE; SymbolCreator: x0199378
Q2 Q3 = CMP-0001223-3: MOSFET N-CHANNEL 600V 26A TO220; PartNumber: IPP60R070CFD7XKSA1; Alternate Manufacturer: None; Manufacturer: Infineon Technologies; SizeZ_mm: 19.4; ChType: N; Value2: 65 nC; VdsMax_V: 650V; SizeX_mm: 10.2; SizeY_mm: 4.5; Vgs_V: 20V; QgTyp_nC: 65; SizeArea_mm2: 45.9; AEC Category: Q101; IdsMax_A: 31A; SizeAreaWB_mm2: 79.3; U/M: EA
Q4 = CMP-0000488-2: Transistor, NPN, 60 V, 0.5 A, AEC-Q101, SOT-23; Manufacturer: ON Semiconductor; TaMax_C: 150°C; Value1: 0.5 A; Vcesat1_V: 2.5dV; SizeX_mm: 2.5; SizeY_mm: 3; TaMin_C: -55°C; IcRated_A: 5dA; CompType: BJT; SizeZ_mm: 1.1; AEC Qualified: Y; SizeArea_mm2: 7.5; NPN: 1; Vceo_V: 60V; PNP: 0; AEC Category: Q101; SizeAreaWB_mm2: 14; U/M: EA
Q5 Q7 = CMP-0000955-2: MOSFET, N-CH, 100 V, 100 A, KCS0003B (TO-220-3); Alternate Manufacturer: None; Manufacturer: Texas Instruments; SizeZ_mm: 20.45; ChType: N; Value2: 38 nC; VdsMax_V: 100V; SizeX_mm: 4.55; SizeY_mm: 10.16; Vgs_V: 20V; QgTyp_nC: 38; SizeArea_mm2: 46.228; AEC Category: Q101; IdsMax_A: 100A; SizeAreaWB_mm2: 79.648; U/M: EA
Q6 = CMP-0000421-2: Transistor, NPN, 30 V, 0.6 A, SOT-23; Manufacturer: ON Semiconductor; TaMax_C: 150°C; Value2: 300; Value1: 0.6 A; Vcesat1_V: 1.6V; SizeX_mm: 2.5; SizeY_mm: 3; TaMin_C: -55°C; IcRated_A: 6dA; CompType: BJT; SizeZ_mm: 1.1; SizeArea_mm2: 7.5; NPN: 1; Vceo_V: 30V; PNP: 0; AEC Category: Q101; SizeAreaWB_mm2: 14; U/M: EA
Q13 Q14 = CMP-0000317-2: Transistor, PNP, 30 V, 0.1 A, SOT-23; Manufacturer: Diodes Inc.; CompType: BJT; PNP: 1; NPN: 0; Vceo_V: 30V; Vcesat1_V: 75mV; IcRated_A: 100mA; Value1: 0.1 A; HfeMax: 600; TaMin_C: -65°C; TaMax_C: 150°C; U/M: EA; AEC Category: Q101; SizeArea_mm2: 7.5; SizeAreaWB_mm2: 14; SizeX_mm: 2.5; SizeY_mm: 3; SizeZ_mm: 1.1
R1 = CMP-0023343-3: RES, 0, 1%, 0.1 W, AEC-Q200 Grade 0, 0603; Manufacturer: Stackpole Electronics Inc; Power_W: 100mW; TempCo: ppm/C; U/M: EA; Value: 0; SizeX_mm: 1.6; SizeY_mm: 0.8; SizeZ_mm: 1; Value2: 0.1W; SizeArea_mm2: 1.28; AEC Qualified: Y; AEC Category: Q200
R2 = CMP-0022703-3: RES, 4.53 k, 1%, 0.1 W, AEC-Q200 Grade 0, 0603; Manufacturer: Panasonic; Power_W: 100mW; TempCo: 100 ppm/C; Value_Code: 4k53; U/M: EA; Value: 4.53k; EIA_Code: E96; SizeX_mm: 1.6; SizeY_mm: 0.8; SizeZ_mm: 1; Value2: 0.1W; SizeArea_mm2: 1.28; AEC Qualified: Y; VDC_V: 75V; AEC Grade: 0; AEC Category: Q200
R3 = CMP-0020904-3: RES, 150, 1%, 0.125 W, AEC-Q200 Grade 0, 0805; Manufacturer: Vishay-Dale; Power_W: 125mW; TempCo: 100 ppm/C; Value_Code: 150R; Value: 150; EIA_Code: E96; SizeX_mm: 2; SizeY_mm: 1.25; SizeZ_mm: 1.45; Value2: 0.125W; SizeArea_mm2: 2.5; AEC Qualified: Y; VDC_V: 150V; AEC Category: Q200; AEC Grade: 0
R9 = CMP-0022426-4: RES, 44.2 k, 1%, 0.1 W, AEC-Q200 Grade 0, 0603; Manufacturer: Vishay-Dale; Power_W: 100mW; TempCo: 100 ppm/C; Value_Code: 44k2; Value: 44.2k; EIA_Code: E96; SizeX_mm: 1.6; SizeY_mm: 0.8; SizeZ_mm: 1; Value2: 0.1W; SizeArea_mm2: 1.28; AEC Qualified: Y; VDC_V: 75V; AEC Category: Q200; AEC Grade: 0
R10 R22 R31 = CMP-0016687-3: RES, 1.00 k, 1%, 0.25 W, AEC-Q200 Grade 0, 1206; PartNumber: CRCW12061K00FKEA; Manufacturer: Vishay-Dale; Value: 1.00k; Res_ohm: 1k; Value_Code: 1k00; Power_W: 250mW; Value2: 0.25W; VDC_V: 200V; TempCo: 100 ppm/C; SizeArea_mm2: 5.12; SizeX_mm: 3.2; SizeY_mm: 1.6; SizeZ_mm: 1.35; EIA_Code: E96; AEC Category: Q200; AEC Qualified: Y; AEC Grade: 0
R12 = CMP-0023306-5: RES, 8.06 k, 1%, 0.1 W, 0603; Manufacturer: Yageo; Power_W: 100mW; TempCo: 100 ppm/C; Value_Code: 8k06; Value: 8.06k; EIA_Code: E96; SizeX_mm: 1.6; SizeY_mm: 0.8; SizeZ_mm: 1; Value2: 0.1W; SizeArea_mm2: 1.28; AEC Qualified: N; VDC_V: 75V; AEC Category: Q200; SizeAreaWB_mm2: 4.68
R17 = CMP-0022779-5: RES, 12.0 k, 1%, 0.1 W, 0603; Manufacturer: Yageo; Power_W: 100mW; TempCo: 100 ppm/C; Value_Code: 12k0; Value: 12.0k; Res_ohm: 12k; SizeX_mm: 1.6; SizeY_mm: 0.8; SizeZ_mm: 1; Value2: 0.1W; SizeArea_mm2: 1.28; AEC Qualified: N; VDC_V: 75V; AEC Category: Q200; SizeAreaWB_mm2: 4.68
R25 = CMP-0024929-2: RES, 213 k, 0.5%, 0.1 W, 0603; Manufacturer: Yageo America; Power_W: 100mW; TempCo: 50 ppm/C; U/M: EA; Value: 213k; EIA_Code: E192; SizeX_mm: 1.6; SizeY_mm: 0.8; SizeZ_mm: 1; Value2: 0.1W; SizeArea_mm2: 1.28; VDC_V: 75V; AEC Category: Q200
R29 R36 = CMP-0018656-3: RES, 330 k, 5%, 0.25 W, AEC-Q200 Grade 0, 1206; PartNumber: CRCW1206330KJNEA; Manufacturer: Vishay-Dale; Value: 330k; Power_W: 250mW; Value2: 0.25W; VDC_V: 200V; TempCo: 200 ppm/C; EIA_Code: E24; AEC Category: Q200; AEC Grade: 0; AEC Qualified: Y; SizeArea_mm2: 5.12; SizeX_mm: 3.2; SizeY_mm: 1.6; SizeZ_mm: 1.35
R32 = CMP-0022768-4: RES, 120 k, 1%, 0.1 W, 0603; Manufacturer: Yageo; Power_W: 100mW; TempCo: 100 ppm/C; Value: 120k; SizeX_mm: 1.6; SizeY_mm: 0.8; SizeZ_mm: 1; Value2: 0.1W; SizeArea_mm2: 1.28; AEC Qualified: N; VDC_V: 75V; AEC Category: Q200; SizeAreaWB_mm2: 4.68
R38 R40 = CMP-0025758-4: RES, 22, 5%, 0.1 W, AEC-Q200 Grade 0, 0603; PartNumber: CRCW060322R0JNEA; Manufacturer: Vishay-Dale; Value: 22; Value_Code: 22R0; Power_W: 100mW; Value2: 0.1W; VDC_V: 75V; TempCo: 200 ppm/C; SizeArea_mm2: 1.28; SizeX_mm: 1.6; SizeY_mm: 0.8; SizeZ_mm: 1; EIA_Code: E24; AEC Category: Q200; AEC Qualified: Y; AEC Grade: 0
R43 = CMP-0018656-2: RES, 330 k, 5%, 0.25 W, 1206; Manufacturer: Vishay-Dale; Power_W: 250mW; TempCo: 200 ppm/C; U/M: EA; Value: 330k; EIA_Code: E24; SizeX_mm: 3.2; SizeY_mm: 1.6; SizeZ_mm: 1.35; Value2: 0.25W; SizeArea_mm2: 5.12; VDC_V: 200V; AEC Category: Q200
R44 R45 = CMP-0025696-3: RES, 4.7 k, 5%, 0.1 W, 0603; PartNumber: CR0603-JW-472GLF; Manufacturer: Bourns; Value: 4.7k; Value_Code: 4k70; Power_W: 100mW; Value2: 0.1W; VDC_V: 50V; TempCo: 200 ppm/C; EIA_Code: E24; U/M: EA; AEC Category: Q200; AEC Qualified: N; SizeArea_mm2: 1.28; SizeX_mm: 1.6; SizeY_mm: 0.8; SizeZ_mm: 1
R47 R71 R73 = CMP-0022558-4: RES, 6.04 k, 1%, 0.1 W, AEC-Q200 Grade 0, 0603; PartNumber: CRCW06036K04FKEA; Manufacturer: Vishay-Dale; Value: 6.04k; Value_Code: 6k04; Power_W: 100mW; Value2: 0.1W; VDC_V: 75V; TempCo: 100 ppm/C; SizeArea_mm2: 1.28; SizeX_mm: 1.6; SizeY_mm: 0.8; SizeZ_mm: 1; EIA_Code: E96; AEC Category: Q200; AEC Qualified: Y; AEC Grade: 0
R48 = CMP-0022052-4: RES, 147 k, 1%, 0.1 W, AEC-Q200 Grade 0, 0603; PartNumber: CRCW0603147KFKEA; Manufacturer: Vishay-Dale; Value: 147k; Power_W: 100mW; Value2: 0.1W; VDC_V: 75V; TempCo: 100 ppm/C; SizeArea_mm2: 1.28; SizeX_mm: 1.6; SizeY_mm: 0.8; SizeZ_mm: 1; EIA_Code: E96; AEC Category: Q200; AEC Qualified: Y; AEC Grade: 0
R49 = CMP-0021998-4: RES, 10.0 k, 1%, 0.1 W, AEC-Q200 Grade 0, 0603; PartNumber: CRCW060310K0FKEA; Manufacturer: Vishay-Dale; Value: 10.0k; Res_ohm: 10k; Value_Code: 10k0; Power_W: 100mW; Value2: 0.1W; VDC_V: 75V; TempCo: 100 ppm/C; SizeArea_mm2: 1.28; SizeX_mm: 1.6; SizeY_mm: 0.8; SizeZ_mm: 1; EIA_Code: E96; AEC Category: Q200; AEC Qualified: Y; AEC Grade: 0
R50 = CMP-0022790-5: RES, 13.3 k, 1%, 0.1 W, 0603; Manufacturer: Yageo; Power_W: 100mW; TempCo: 100 ppm/C; Value_Code: 13k3; Value: 13.3k; EIA_Code: E96; SizeX_mm: 1.6; SizeY_mm: 0.8; SizeZ_mm: 1; Value2: 0.1W; SizeArea_mm2: 1.28; AEC Qualified: N; VDC_V: 75V; AEC Category: Q200; SizeAreaWB_mm2: 4.68
R51 R63 = CMP-0022010-4: RES, 113 k, 1%, 0.1 W, AEC-Q200 Grade 0, 0603; Manufacturer: Vishay-Dale; Power_W: 100mW; TempCo: 100 ppm/C; Value: 113k; EIA_Code: E96; SizeX_mm: 1.6; SizeY_mm: 0.8; SizeZ_mm: 1; Value2: 0.1W; SizeArea_mm2: 1.28; AEC Qualified: Y; VDC_V: 75V; AEC Category: Q200; AEC Grade: 0
R52 R53 = CMP-0020448-3: RES, 10, 5%, 0.125 W, AEC-Q200 Grade 0, 0805; PartNumber: CRCW080510R0JNEA; Manufacturer: Vishay-Dale; Value: 10; Value_Code: 10R0; Power_W: 125mW; Value2: 0.125W; VDC_V: 150V; TempCo: 200 ppm/C; EIA_Code: E24; AEC Category: Q200; AEC Grade: 0; AEC Qualified: Y; SizeArea_mm2: 2.5; SizeX_mm: 2; SizeY_mm: 1.25; SizeZ_mm: 1.45
R55 R64 = CMP-0023626-3: RES, 10.0 k, 0.01%, 0.063 W, 0603; PartNumber: RNCF0603TKY10K0; Manufacturer: Stackpole Electronics Inc; Value: 10.0k; Res_ohm: 10k; Value_Code: 10k0; Power_W: 63mW; Value2: 0.063W; VDC_V: 50V; TempCo: 5 ppm/C; U/M: EA; AEC Category: Q200; SizeArea_mm2: 1.28; SizeX_mm: 1.6; SizeY_mm: 0.8; SizeZ_mm: 1
R56 = CMP-0023630-3: RES, 100 k, 0.1%, 0.1 W, 0603; Manufacturer: Yageo America; Power_W: 100mW; TempCo: 25 ppm/C; U/M: EA; Value: 100k; EIA_Code: E192; SizeX_mm: 1.6; SizeY_mm: 0.8; SizeZ_mm: 1; Value2: 0.1W; SizeArea_mm2: 1.28; VDC_V: 75V; AEC Category: Q200
R60 R61 = CMP-0020563-3: RES, 4.7, 5%, 0.125 W, AEC-Q200 Grade 0, 0805; PartNumber: CRCW08054R70JNEA; Manufacturer: Vishay-Dale; Value: 4.7; Value_Code: 4R70; Power_W: 125mW; Value2: 0.125W; VDC_V: 150V; TempCo: 200 ppm/C; EIA_Code: E24; AEC Category: Q200; AEC Grade: 0; AEC Qualified: Y; SizeArea_mm2: 2.5; SizeX_mm: 2; SizeY_mm: 1.25; SizeZ_mm: 1.45
R62 = CMP-0023252-5: RES, 6.81 k, 1%, 0.1 W, 0603; Manufacturer: Yageo; Power_W: 100mW; TempCo: 100 ppm/C; Value_Code: 6k81; Value: 6.81k; EIA_Code: E96; SizeX_mm: 1.6; SizeY_mm: 0.8; SizeZ_mm: 1; Value2: 0.1W; SizeArea_mm2: 1.28; AEC Qualified: N; VDC_V: 75V; AEC Category: Q200; SizeAreaWB_mm2: 4.68
R65 = CMP-0015849-2: RES, 0.001, 1%, 2 W, 2512; Manufacturer: Vishay-Dale; Power_W: 2W; TempCo: 400 ppm/C; Value_Code: R0010; U/M: EA; Value: 0.001; SizeX_mm: 6.35; SizeY_mm: 3.18; SizeZ_mm: 0.89; SizeArea_mm2: 20.193; AEC Qualified: N; AEC Category: Q200
R66 R78 = CMP-0022004-4: RES, 10.0, 1%, 0.25 W, AEC-Q200 Grade 0, 0603; Manufacturer: Vishay-Dale; Power_W: 250mW; TempCo: 100 ppm/C; Value_Code: 10R0; Value: 10.0; EIA_Code: E96; Res_ohm: 10; SizeX_mm: 1.6; SizeY_mm: 0.8; SizeZ_mm: 1; Value2: 0.25W; SizeArea_mm2: 1.28; AEC Qualified: Y; VDC_V: 75V; AEC Category: Q200; AEC Grade: 0
R67 = CMP-0020980-3: RES, 1.00 M, 1%, 0.125 W, AEC-Q200 Grade 0, 0805; Manufacturer: Vishay-Dale; Power_W: 125mW; TempCo: 100 ppm/C; Value_Code: 1M00; Value: 1.00Meg; EIA_Code: E96; Res_ohm: 1M; SizeX_mm: 2; SizeY_mm: 1.25; SizeZ_mm: 1.45; Value2: 0.125W; AEC Qualified: Y; VDC_V: 150V; AEC Category: Q200; SizeArea_mm2: 2.5; AEC Grade: 0
R68 = CMP-0023070-4: RES, 392 k, 1%, 0.1 W, 0603; Manufacturer: Yageo; Power_W: 100mW; TempCo: 100 ppm/C; Value: 392k; EIA_Code: E96; SizeX_mm: 1.6; SizeY_mm: 0.8; SizeZ_mm: 1; Value2: 0.1W; SizeArea_mm2: 1.28; AEC Qualified: N; VDC_V: 75V; AEC Category: Q200; SizeAreaWB_mm2: 4.68
R69 = CMP-0022697-2: RES, 330 k, 1%, 0.1 W, AEC-Q200 Grade 0, 0603; Manufacturer: Panasonic; Power_W: 100mW; TempCo: 100 ppm/C; U/M: EA; Value: 330k; SizeX_mm: 1.6; SizeY_mm: 0.8; SizeZ_mm: 1; Value2: 0.1W; SizeArea_mm2: 1.28; AEC Qualified: Y; VDC_V: 75V; AEC Grade: 0; AEC Category: Q200
R70 = CMP-0022441-4: Manufacturer: Vishay-Dale; Res_ohm: 487k; Tolerance_%: 1%; Power_W: 100mW; Value2: 0.1W; VDC_V: 75V; TempCo: 100 ppm/C; EIA_Code: E96; AEC Category: Q200; AEC Grade: 0; AEC Qualified: Y; SizeArea_mm2: 1.28; SizeX_mm: 1.6; SizeY_mm: 0.8; SizeZ_mm: 1
R72 = CMP-0023289-4: RES, 825 k, 1%, 0.1 W, 0603; Manufacturer: Yageo; Power_W: 100mW; TempCo: 100 ppm/C; Value: 825k; EIA_Code: E96; SizeX_mm: 1.6; SizeY_mm: 0.8; SizeZ_mm: 1; Value2: 0.1W; SizeArea_mm2: 1.28; AEC Qualified: N; VDC_V: 75V; AEC Category: Q200; SizeAreaWB_mm2: 4.68
R100 R101 = CMP-0022680-4: RES, 1.00 k, 1%, 0.1 W, 0603; Manufacturer: Panasonic; Power_W: 100mW; TempCo: 100 ppm/C; Value_Code: 1k00; U/M: EA; Value: 1.00k; EIA_Code: E96; Res_ohm: 1k; SizeX_mm: 1.6; SizeY_mm: 0.8; SizeZ_mm: 1; SizeArea_mm2: 1.28; VDC_V: 75V; AEC Category: Q200; Value2: 0.1W
T1 = CMP-0088745-1: TRANSFORMER; Manufacturer: Wurth Electronics; Rsec1_ohm: 8m; Ns1toNp: 4:1/4:1/6:1; SizeZ_mm: 31.75mm; Frequency_Fixed: 100kHz; Ind_H: 102µH; AEC Qualified: No; Voltage_Isolation_Vrms: 3kV; DCR_ohm: 19m
U2 = CMP-0013274-1: Switching Controllers LLC resonant controller with ultra-low power, ultra-quiet standby operation and high voltage startup 14-SOIC -40 to 125; Manufacturer: Texas Instruments; SizeArea_mm2: 59.4; SizeAreaWB_mm2: 95.2; SizeX_mm: 6; SizeY_mm: 9.9; SizeZ_mm: 1.75; CompType: IC; U/M: EA
U4 = CMP-0036254-1: Single Output LDO, 100 mA, 1.2 to 29 V Output, 2 to 30 V Input, -40 to 125 degC, 8-Pin SOIC (D), RoHS, Tape and Reel; Manufacturer: Texas Instruments; Accuracy (%): 1.4; Output Options: Adjustable Output; Iout (Max) (A): 0.1; Vin (Max) (V): 30; Iq (Typ) (mA): 0.075; Vdo (Typ) (mV): 380; Vout (Max) (V): 29; Vin (Min) (V): 2; Output Capacitor Type: Non-Ceramic; Vout (Min) (V): 1.2; Rating: Catalog
U5 = CMP-0084729-1: Programmable Shunt Regulator with Optimized Reference Current, DBZ0003A (SOT-23-3); Manufacturer: Texas Instruments; SizeY_mm: 3; SizeZ_mm: 1.12; SizeX_mm: 2.5; SizeAreaWB_mm2: 14; CompType: IC; AEC Qualified: N; AEC Category: Q200; SizeArea_mm2: 7.5
U6 = CMP-0006187-3: Optocoupler, 5.3 kV, 50-600% CTR, TH; PartNumber: VO618A-3; Manufacturer: Vishay-Semiconductor; CTR (Min): 50%; CTR (Max): 600%; Voltage_Isolation_Vrms: 5.3kV; SizeAreaWB_mm2: 71.064; SizeArea_mm2: 40.304; SizeX_mm: 8.8; SizeY_mm: 4.58; SizeZ_mm: 5; Value: VO618A-3
U7 U8 = CMP-0013050-3: High-Frequency Multi-Mode Synchronous Rectifier Controller, DBV0005A (SOT-23-5); Alternate PartNumber: UCC24612-1DBVT; Manufacturer: Texas Instruments; SizeArea_mm2: 8.12; SizeAreaWB_mm2: 14.82; SizeX_mm: 2.8; SizeY_mm: 2.9; SizeZ_mm: 1.45; CompType: IC; AEC Category: Q200; AEC Qualified: N
U10 = CMP-0070878-1: Micropower 100 mA Ultra Low-Dropout Regulator, 5-pin SOT-23, Pb-Free; Manufacturer: Texas Instruments; PartNumber: LP2981-50DBVR; CompType: LDO IC; PowerWise: N; PackageTopMarking: L05B*XTT
U11 = CMP-0089970-1: Single Differential Comparator; Manufacturer: Texas Instruments; Min Supply Voltage: 3V; Response Time: 1us; Voltage Gain: 200V/mV; Nominal Supply Current: 210-275uA; AEC Qualified: No; SizeZ_mm: 1.45mm; TJmax_C: +125°C; Standoff Height: 0mm; Input Offset Voltage: 0.37mV; Max Supply Voltage: 36V; Number Of Channels: 1; Output Current Per Channel: 20mA; Input Bias Current: -0.0035uA
U12 = CMP-0006187-3: Optocoupler, 5.3 kV, 50-600% CTR, TH; PartNumber: VO618A; Manufacturer: Vishay-Semiconductor; CTR (Min): 50%; CTR (Max): 600%; Voltage_Isolation_Vrms: 5.3kV; SizeAreaWB_mm2: 71.064; SizeArea_mm2: 40.304; SizeX_mm: 8.8; SizeY_mm: 4.58; SizeZ_mm: 5; Value: VO618A
U14 = CMP-0013228-2: Bidirectional, Low- and High-Side Measurement, Multichannel, Voltage Output, Current-Sense Amplifier, DBV0006A (SOT-6); Manufacturer: Texas Instruments; SizeX_mm: 2.8; SizeY_mm: 2.9; CompType: IC; SizeZ_mm: 1.45; SizeArea_mm2: 8.12; SizeAreaWB_mm2: 14.82; U/M: EA

## Sheet PMP31179 Rev_A Hardware.SchDoc: Hardware
size 431 x 279 mm; Date: Not shown in title block; ApprovedBy: Not shown in title block; CheckedBy: Not shown in title block; Author: Not shown in title block; CompanyName: Not shown in title block; DrawnBy: R. Scibilia; Engineer: R. Scibilia; Organization: Not shown in title block; Address1: Not shown in title block; Address2: Not shown in title block; Address3: Not shown in title block; Address4: Not shown in title block; DocumentNumber: 1; Revision: Use project parameter SCH_Rev; SheetNumber: 3; SheetTotal: 3; PageSetup: Record=PageOptions¦CenterHorizontal=True¦CenterVertical=True¦PrintScale=1.00¦XCorrection=1.00¦YCorrection=1.00¦PrintKind=0¦BorderSize=5000000¦LeftOffset=0¦BottomOffset=0¦Orientation=2¦PaperLength=1000¦PaperWidth=1000¦Scale=100¦PaperSource=15¦PrintQuality=600¦MediaType=1¦DitherType=10¦PaperKind=Letter¦PrintScaleMode=1
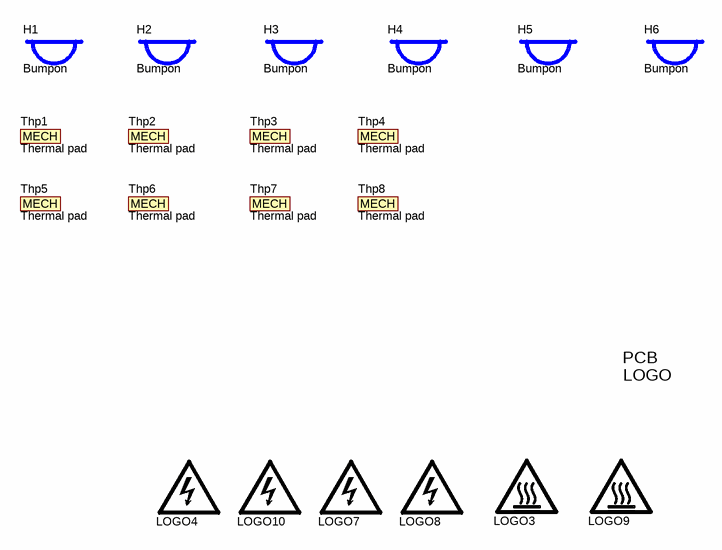
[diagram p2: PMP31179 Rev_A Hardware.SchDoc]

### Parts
H1  Bumpon  [Bumpon_SJ5003Transparent]
H2  Bumpon  [Bumpon_SJ5003Transparent]
H3  Bumpon  [Bumpon_SJ5003Transparent]
H4  Bumpon  [Bumpon_SJ5003Transparent]
H5  Bumpon  [Bumpon_SJ5003Transparent]
H6  Bumpon  [Bumpon_SJ5003Transparent]
Logo2  ESD Susceptible  [ESD_Overlay_Small]  (value not drawn)  (no BOM)
LOGO3  CAUTION HOT SURFACE  [IEC_HotSurface_Small]  (value not drawn)  (no BOM)
LOGO4  DANGER HIGH VOLTAGE  [IEC_HighVoltage_Small]  (value not drawn)  (no BOM)
LOGO7  DANGER HIGH VOLTAGE  [IEC_HighVoltage_Small]  (value not drawn)  (no BOM)
LOGO8  DANGER HIGH VOLTAGE  [IEC_HighVoltage_Small]  (value not drawn)  (no BOM)
LOGO9  CAUTION HOT SURFACE  [IEC_HotSurface_Small]  (value not drawn)  (no BOM)
LOGO10  DANGER HIGH VOLTAGE  [IEC_HighVoltage_Small]  (value not drawn)  (no BOM)
Thp1  value Thermal pad  (hidden comment: CP23-TO220-21.5-11.4-5.8-0.3)  (mechanical)
Thp2  value Thermal pad  (hidden comment: CP23-TO220-21.5-11.4-5.8-0.3)  (mechanical)
Thp3  value Thermal pad  (hidden comment: CP23-TO220-21.5-11.4-5.8-0.3)  (mechanical)
Thp4  value Thermal pad  (hidden comment: CP23-TO220-21.5-11.4-5.8-0.3)  (mechanical)
Thp5  value Thermal pad  (hidden comment: CP23-TO220-21.5-11.4-5.8-0.3)  (mechanical)
Thp6  value Thermal pad  (hidden comment: CP23-TO220-21.5-11.4-5.8-0.3)  (mechanical)
Thp7  value Thermal pad  (hidden comment: CP23-TO220-21.5-11.4-5.8-0.3)  (mechanical)
Thp8  value Thermal pad  (hidden comment: CP23-TO220-21.5-11.4-5.8-0.3)  (mechanical)

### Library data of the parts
H1-H6 = CMP-0003620-1: Bumpon, Hemisphere, 0.44 X 0.20, Clear; Manufacturer: 3M; PartNumber: SJ-5303 (CLEAR)
Logo2 = CMP-0074840-1: ESD Susceptible Symbol; SymbolCreator: a0412235; Lib Reference: ESD_Susceptible
LOGO3 LOGO9 = CMP-0074837-1: IEC 61010-1 Hot Surface Warning; SymbolCreator: a0412235
LOGO4 LOGO7 LOGO8 LOGO10 = CMP-0074835-1: IEC 61010-1 High Voltage Warning; SymbolCreator: a0412235
Thp1-Thp8 = CMP-0003816-1: THERM PAD 21.5MMX11.4MMX5.8MM; Manufacturer: Keystone; Key: 4662; CompType: Insulator

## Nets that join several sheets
12V: PMP31179 Rev_A PFC Schematic (C64.1 Q8.2 R79.1), PMP31179 Rev_A LLC Schematic (6 pins)
AUX_15V: PMP31179 Rev_A PFC Schematic (10 pins), PMP31179 Rev_A LLC Schematic (C51.1 R51.2 U4.1)
PGND: PMP31179 Rev_A PFC Schematic (65 pins), PMP31179 Rev_A LLC Schematic (29 pins)
Vpfc: PMP31179 Rev_A PFC Schematic (10 pins), PMP31179 Rev_A LLC Schematic (C2.1 Q3.2 R43.2)
NetA: PMP31179 Rev_A PFC Schematic (D9.1 D10.1 R28.1), PMP31179 Rev_A LLC Schematic (R31.1)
